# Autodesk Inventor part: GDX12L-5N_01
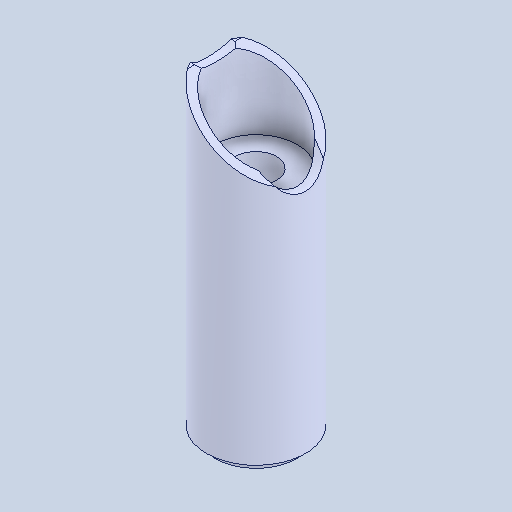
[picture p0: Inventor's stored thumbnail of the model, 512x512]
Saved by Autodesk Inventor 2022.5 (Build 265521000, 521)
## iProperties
Created: 2024-06
Part Number: GDX12L-5N_01
Material: 一般
Document SubType Name: Modeling
Designer: ImaoCorp
Density: 1 g/cm^3
Appearance: 既定
Author: ImaoCorp
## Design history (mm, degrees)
feature "GDX12L-5N_01"
node "ソリッド1"
